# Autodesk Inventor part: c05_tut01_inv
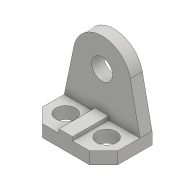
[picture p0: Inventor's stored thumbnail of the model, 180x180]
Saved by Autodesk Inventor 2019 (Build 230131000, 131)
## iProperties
Created: 2017-04
Part Number: c05_tut01_inv
Material: Generic
Document SubType Name: Modeling
Designer: CADCIM 00
Density: 1 g/cm^3
Appearance: Default
Author: CADCIM 00
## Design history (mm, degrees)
sketch "Sketch1"
  geometry: L1 (0, 0)-(-200, 0); L2 (-200, 0)-(-200, -90); L3 (-200, -90)-(-162, -128); L4 (-162, -128)-(-38, -128); L5 (-38, -128)-(0, -90); L6 (0, -90)-(0, 0); L7 (-200, -90)-(0, -90); C1 r 26 at (-154, -74); C2 r 26 at (-46, -74)
  constraints: 14 end point, 3 horizontal, 3 perpendicular, 2 centre point, 1 equal radius, 1 horizontal alignment
  dimensions: "d0" = 90 distance of L1.end L2.end; "d1" = 128 distance between parallel lines of L1 L4; "d2" = 38 distance from line of L3.end L2; "d3" = 124 distance of L3.end L4.end; "d4" = 46 distance from line of L2 C1.centre; "d5" = 74 distance from line of L1 C1.centre; "d6" = 52 diameter of C1; "d7" = 46 distance from line of L6 C2.centre
extrude "Extrusion1" new body sketch "Sketch1" distance "d8" = 32; taper "d9" = 0 deg
sketch "Sketch2"
  geometry: L1 (200, -32)-(0, -32) reference; L2 (200, -32)-(174.418, -155.424); L3 (25.582, -155.424)-(0, -32); L4 (0, -32)-(200, -32); L5 (100, -32)-(100, -140); C1 r 27.5 at (100, -140); A1 r 76 centre (100, -140) between (25.582, -155.424) and (174.418, -155.424); 1 further point
  constraints: 8 end point, 2 centre point, 2 point on circle, 2 tangent, 1 coincident, 1 collinear, 1 midpoint, 1 vertical
  dimensions: "d10" = 55 diameter of C1; "d11" = 76 radius of A1; "d12" = 108 distance from line of L1 A1.centre
extrude "Extrusion2" join sketch "Sketch2" distance "d13" = 32; taper "d14" = 0 deg
sketch "Sketch3"
  geometry: L1 (82, 42)-(118, 42); L2 (118, 42)-(118, 32); L3 (118, 32)-(82, 32); L4 (82, 32)-(82, 42); L5 (38, 32)-(162, 32) reference; L6 (0, 0)-(0, 32) reference; 1 further point
  constraints: 8 end point, 2 parallel, 1 collinear, 1 horizontal, 1 perpendicular
  dimensions: "d15" = 10 distance between parallel lines of L3 L1; "d16" = 36 distance of L1.start L1.end; "d17" = 82 distance from line of L6 L1.start
extrude "Extrusion3" join sketch "Sketch3" stored distance "d18" = 32; taper "d19" = 0 deg
body "Solid1"
